(* Logix 5000 project; controller MyControlLogix 1756-L63 rev 15.1; software revision 15.02; part 4 of 4 *)
(* tags used below, declared in another part *)
   AFC56 : AFC;
(* MainProgram, continued *)

ROUTINE Prove_Out   (* ladder *)
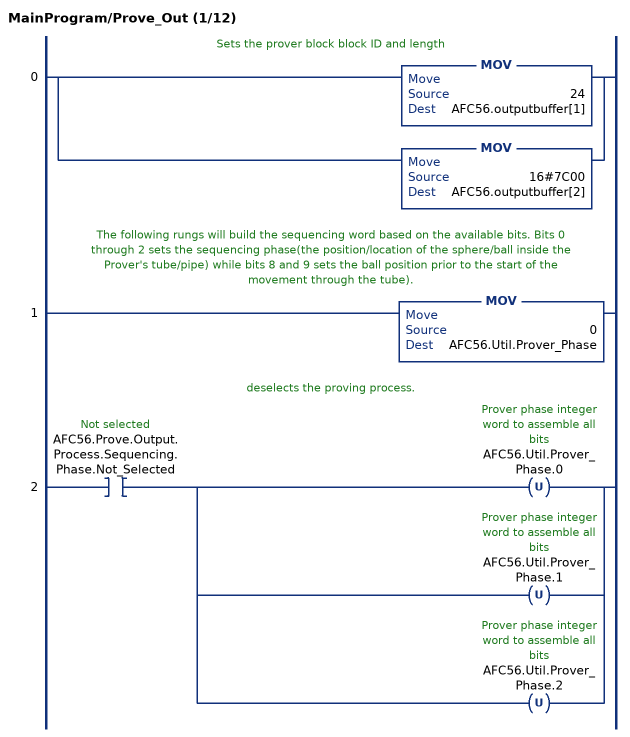
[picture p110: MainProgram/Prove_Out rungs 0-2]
   // Sets the prover block block ID and length
   0: [MOV(24,AFC56.outputbuffer[1]) ,MOV(16#7C00,AFC56.outputbuffer[2]) ];
   // The following rungs will build the sequencing word based on the available bits. Bits 0 through 2 sets the sequencing phase(the position/location of the sphere/ball inside the Prover's tube/pipe) while bits 8 and 9 sets the ball position prior to the start of the movement through the tube).
   1: MOV(0,AFC56.Util.Prover_Phase);
   // deselects the proving process.
   2: XIC(AFC56.Prove.Output.Process.Sequencing.Phase.Not_Selected)[OTU(AFC56.Util.Prover_Phase.0) ,OTU(AFC56.Util.Prover_Phase.1) ,OTU(AFC56.Util.Prover_Phase.2) ];
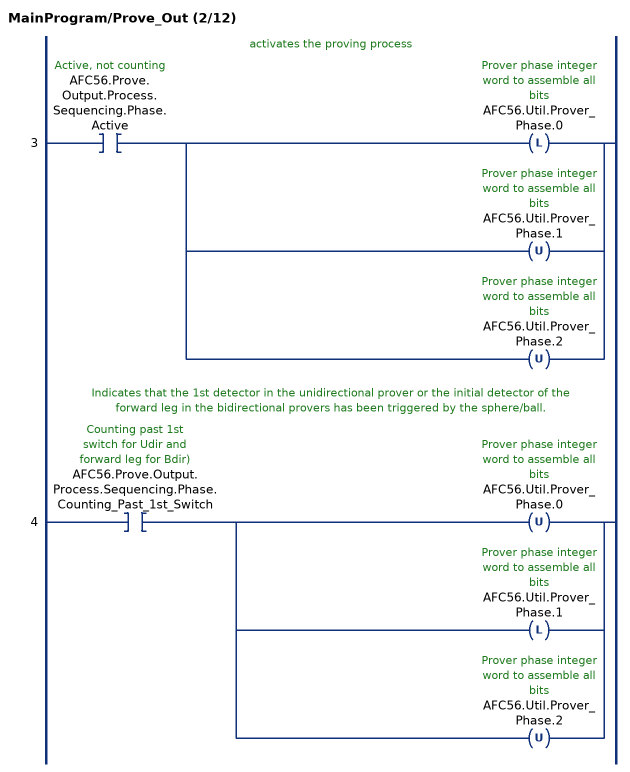
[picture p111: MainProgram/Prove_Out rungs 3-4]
   // activates the proving process
   3: XIC(AFC56.Prove.Output.Process.Sequencing.Phase.Active)[OTL(AFC56.Util.Prover_Phase.0) ,OTU(AFC56.Util.Prover_Phase.1) ,OTU(AFC56.Util.Prover_Phase.2) ];
   // Indicates that the 1st detector in the unidirectional prover or the initial detector of the forward leg in the bidirectional provers has been triggered by the sphere/ball.
   4: XIC(AFC56.Prove.Output.Process.Sequencing.Phase.Counting_Past_1st_Switch)[OTU(AFC56.Util.Prover_Phase.0) ,OTL(AFC56.Util.Prover_Phase.1) ,OTU(AFC56.Util.Prover_Phase.2) ];
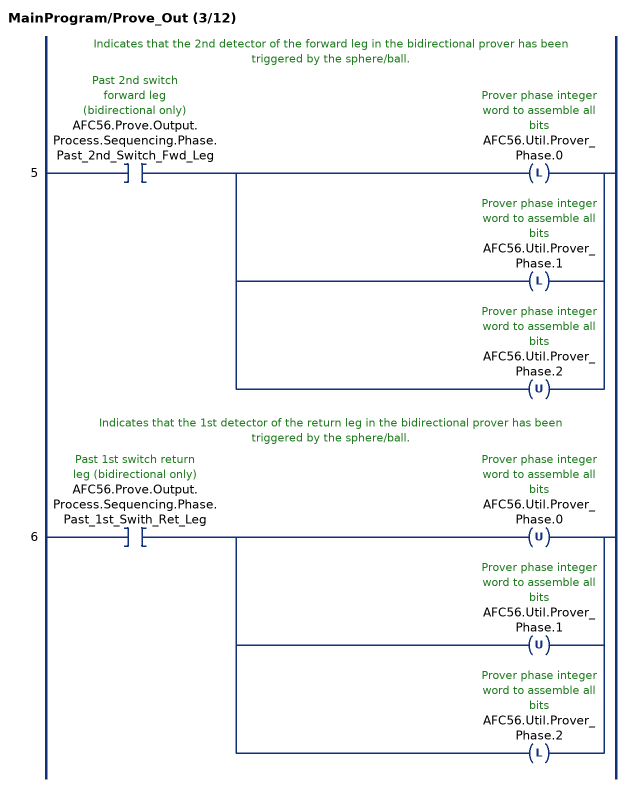
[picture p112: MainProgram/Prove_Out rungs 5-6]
   // Indicates that the 2nd detector of the forward leg in the bidirectional prover has been triggered by the sphere/ball.
   5: XIC(AFC56.Prove.Output.Process.Sequencing.Phase.Past_2nd_Switch_Fwd_Leg)[OTL(AFC56.Util.Prover_Phase.0) ,OTL(AFC56.Util.Prover_Phase.1) ,OTU(AFC56.Util.Prover_Phase.2) ];
   // Indicates that the 1st detector of the return leg in the bidirectional prover has been triggered by the sphere/ball.
   6: XIC(AFC56.Prove.Output.Process.Sequencing.Phase.Past_1st_Swith_Ret_Leg)[OTU(AFC56.Util.Prover_Phase.0) ,OTU(AFC56.Util.Prover_Phase.1) ,OTL(AFC56.Util.Prover_Phase.2) ];
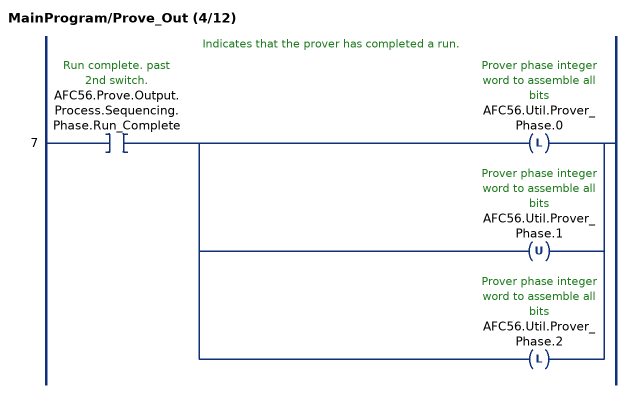
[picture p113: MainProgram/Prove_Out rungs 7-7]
   // Indicates that the prover has completed a run.
   7: XIC(AFC56.Prove.Output.Process.Sequencing.Phase.Run_Complete)[OTL(AFC56.Util.Prover_Phase.0) ,OTU(AFC56.Util.Prover_Phase.1) ,OTL(AFC56.Util.Prover_Phase.2) ];
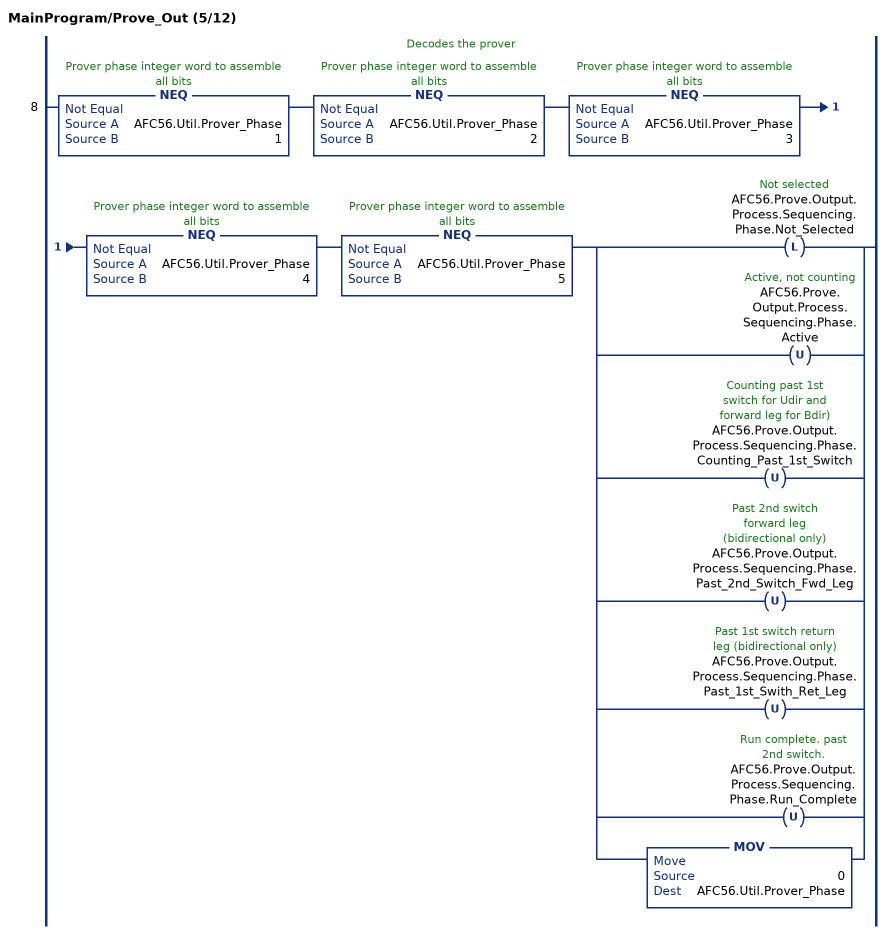
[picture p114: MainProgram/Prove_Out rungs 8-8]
   // Decodes the prover
   8: NEQ(AFC56.Util.Prover_Phase,1)NEQ(AFC56.Util.Prover_Phase,2)NEQ(AFC56.Util.Prover_Phase,3)NEQ(AFC56.Util.Prover_Phase,4)NEQ(AFC56.Util.Prover_Phase,5)[OTL(AFC56.Prove.Output.Process.Sequencing.Phase.Not_Selected) ,OTU(AFC56.Prove.Output.Process.Sequencing.Phase.Active) ,OTU(AFC56.Prove.Output.Process.Sequencing.Phase.Counting_Past_1st_Switch) ,OTU(AFC56.Prove.Output.Process.Sequencing.Phase.Past_2nd_Switch_Fwd_Leg) ,OTU(AFC56.Prove.Output.Process.Sequencing.Phase.Past_1st_Swith_Ret_Leg) ,OTU(AFC56.Prove.Output.Process.Sequencing.Phase.Run_Complete) ,MOV(0,AFC56.Util.Prover_Phase) ];
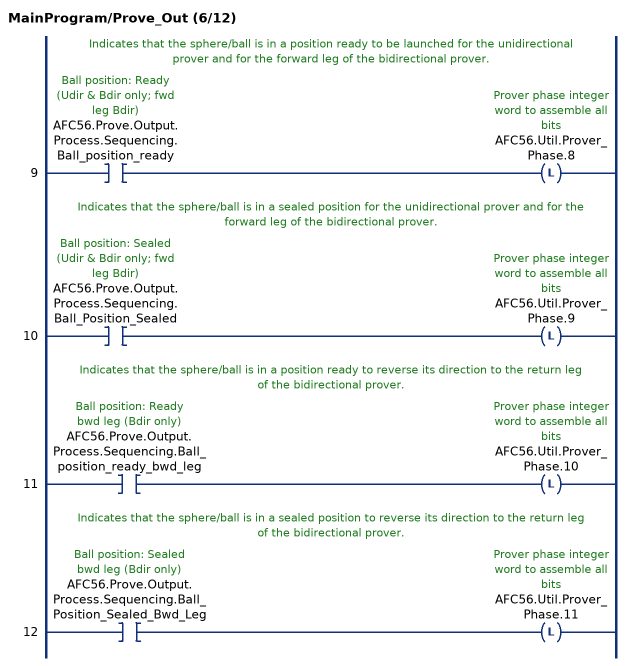
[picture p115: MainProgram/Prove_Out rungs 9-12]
   // Indicates that the sphere/ball is in a position ready to be launched for the unidirectional prover and for the forward leg of the bidirectional prover.
   9: XIC(AFC56.Prove.Output.Process.Sequencing.Ball_position_ready)OTL(AFC56.Util.Prover_Phase.8);
   // Indicates that the sphere/ball is in a sealed position for the unidirectional prover and for the forward leg of the bidirectional prover.
   10: XIC(AFC56.Prove.Output.Process.Sequencing.Ball_Position_Sealed)OTL(AFC56.Util.Prover_Phase.9);
   // Indicates that the sphere/ball is in a position ready to reverse its direction to the return leg of the bidirectional prover.
   11: XIC(AFC56.Prove.Output.Process.Sequencing.Ball_position_ready_bwd_leg)OTL(AFC56.Util.Prover_Phase.10);
   // Indicates that the sphere/ball is in a sealed position to reverse its direction to the return leg of the bidirectional prover.
   12: XIC(AFC56.Prove.Output.Process.Sequencing.Ball_Position_Sealed_Bwd_Leg)OTL(AFC56.Util.Prover_Phase.11);
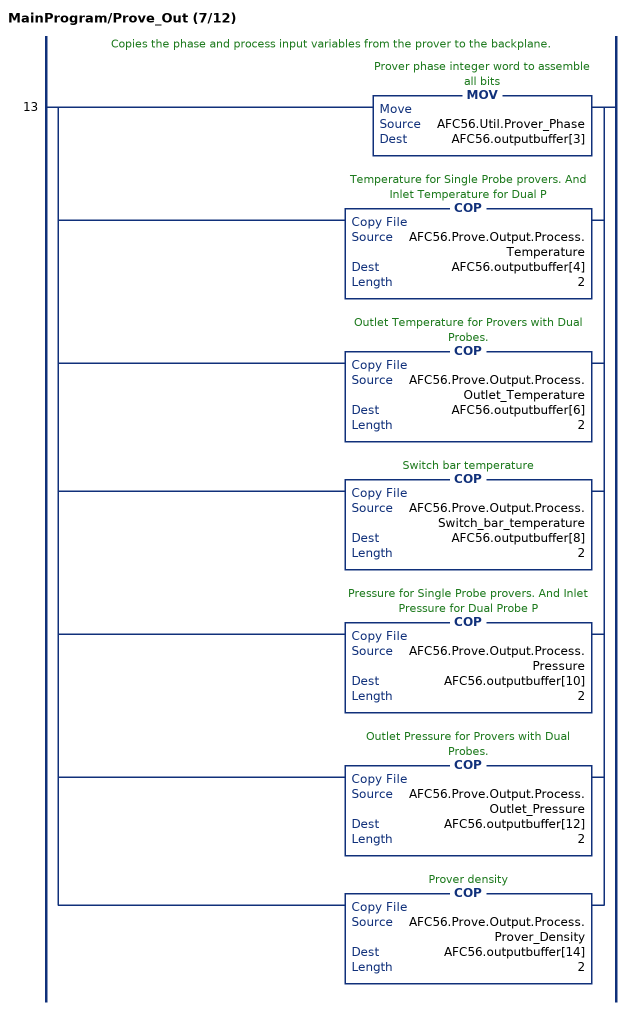
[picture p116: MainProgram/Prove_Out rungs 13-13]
   // Copies the phase and process input variables from the prover to the backplane.
   13: [MOV(AFC56.Util.Prover_Phase,AFC56.outputbuffer[3]) ,COP(AFC56.Prove.Output.Process.Temperature,AFC56.outputbuffer[4],2) ,COP(AFC56.Prove.Output.Process.Outlet_Temperature,AFC56.outputbuffer[6],2) ,COP(AFC56.Prove.Output.Process.Switch_bar_temperature,AFC56.outputbuffer[8],2) ,COP(AFC56.Prove.Output.Process.Pressure,AFC56.outputbuffer[10],2) ,COP(AFC56.Prove.Output.Process.Outlet_Pressure,AFC56.outputbuffer[12],2) ,COP(AFC56.Prove.Output.Process.Prover_Density,AFC56.outputbuffer[14],2) ];
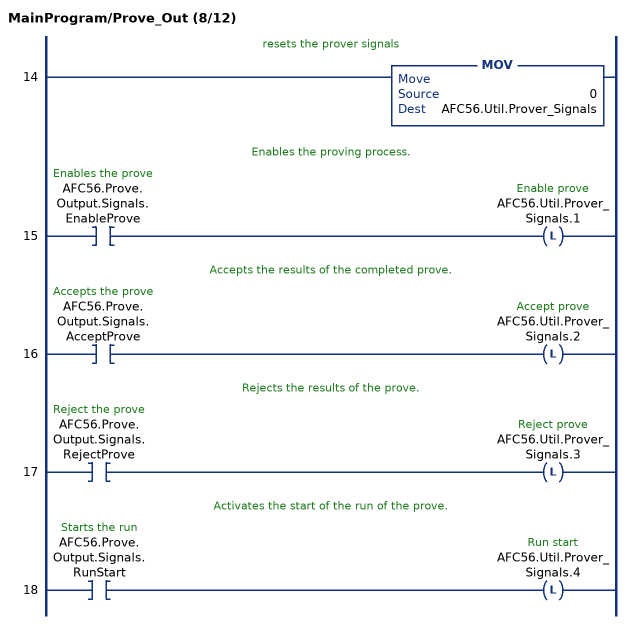
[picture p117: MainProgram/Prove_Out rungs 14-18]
   // resets the prover signals
   14: MOV(0,AFC56.Util.Prover_Signals);
   // Enables the proving process.
   15: XIC(AFC56.Prove.Output.Signals.EnableProve)OTL(AFC56.Util.Prover_Signals.1);
   // Accepts the results of the completed prove.
   16: XIC(AFC56.Prove.Output.Signals.AcceptProve)OTL(AFC56.Util.Prover_Signals.2);
   // Rejects the results of the prove.
   17: XIC(AFC56.Prove.Output.Signals.RejectProve)OTL(AFC56.Util.Prover_Signals.3);
   // Activates the start of the run of the prove.
   18: XIC(AFC56.Prove.Output.Signals.RunStart)OTL(AFC56.Util.Prover_Signals.4);
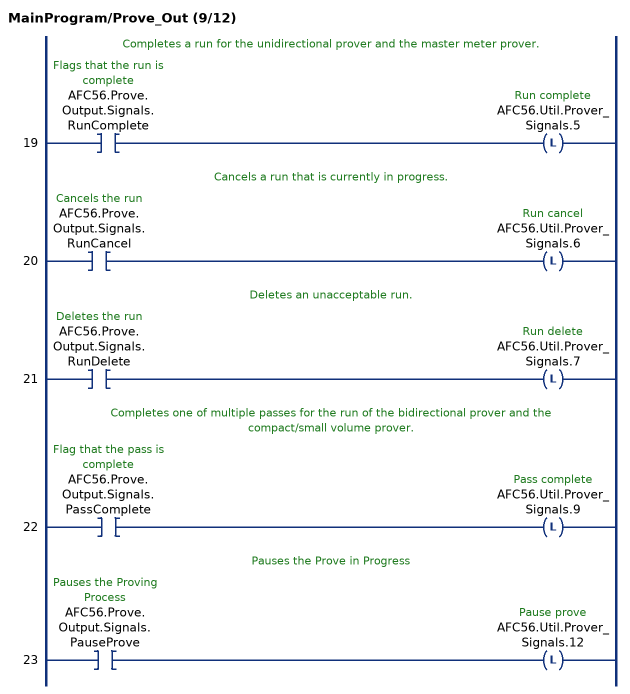
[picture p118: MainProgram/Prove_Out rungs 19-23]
   // Completes a run for the unidirectional prover and the master meter prover.
   19: XIC(AFC56.Prove.Output.Signals.RunComplete)OTL(AFC56.Util.Prover_Signals.5);
   // Cancels a run that is currently in progress.
   20: XIC(AFC56.Prove.Output.Signals.RunCancel)OTL(AFC56.Util.Prover_Signals.6);
   // Deletes an unacceptable run.
   21: XIC(AFC56.Prove.Output.Signals.RunDelete)OTL(AFC56.Util.Prover_Signals.7);
   // Completes one of multiple passes for the run of the bidirectional prover and the compact/small volume prover.
   22: XIC(AFC56.Prove.Output.Signals.PassComplete)OTL(AFC56.Util.Prover_Signals.9);
   // Pauses the Prove in Progress
   23: XIC(AFC56.Prove.Output.Signals.PauseProve)OTL(AFC56.Util.Prover_Signals.12);
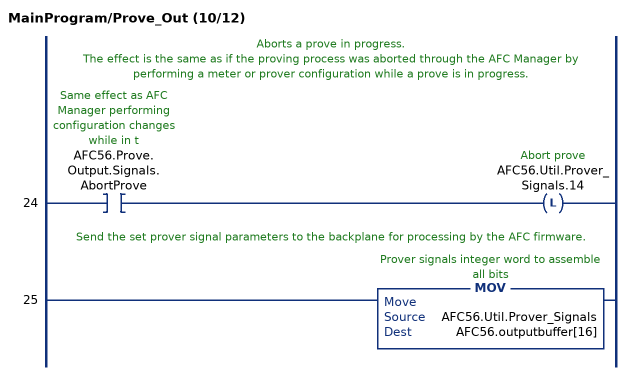
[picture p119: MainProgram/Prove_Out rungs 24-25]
   // Aborts a prove in progress.
   // The effect is the same as if the proving process was aborted through the AFC Manager by performing a meter or prover configuration while a prove is in progress.
   24: XIC(AFC56.Prove.Output.Signals.AbortProve)OTL(AFC56.Util.Prover_Signals.14);
   // Send the set prover signal parameters to the backplane for processing by the AFC firmware.
   25: MOV(AFC56.Util.Prover_Signals,AFC56.outputbuffer[16]);
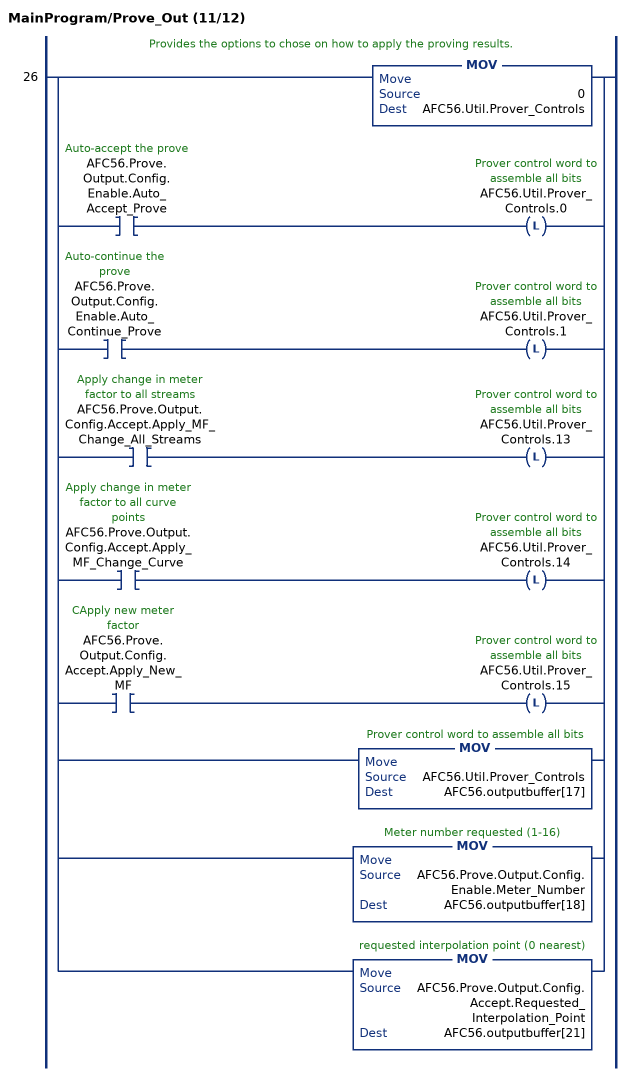
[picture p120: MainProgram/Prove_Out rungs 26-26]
   // Provides the options to chose on how to apply the proving results.
   26: [MOV(0,AFC56.Util.Prover_Controls) ,XIC(AFC56.Prove.Output.Config.Enable.Auto_Accept_Prove) OTL(AFC56.Util.Prover_Controls.0) ,XIC(AFC56.Prove.Output.Config.Enable.Auto_Continue_Prove) OTL(AFC56.Util.Prover_Controls.1) ,XIC(AFC56.Prove.Output.Config.Accept.Apply_MF_Change_All_Streams) OTL(AFC56.Util.Prover_Controls.13) ,XIC(AFC56.Prove.Output.Config.Accept.Apply_MF_Change_Curve) OTL(AFC56.Util.Prover_Controls.14) ,XIC(AFC56.Prove.Output.Config.Accept.Apply_New_MF) OTL(AFC56.Util.Prover_Controls.15) ,MOV(AFC56.Util.Prover_Controls,AFC56.outputbuffer[17]) ,MOV(AFC56.Prove.Output.Config.Enable.Meter_Number,AFC56.outputbuffer[18]) ,MOV(AFC56.Prove.Output.Config.Accept.Requested_Interpolation_Point,AFC56.outputbuffer[21]) ];
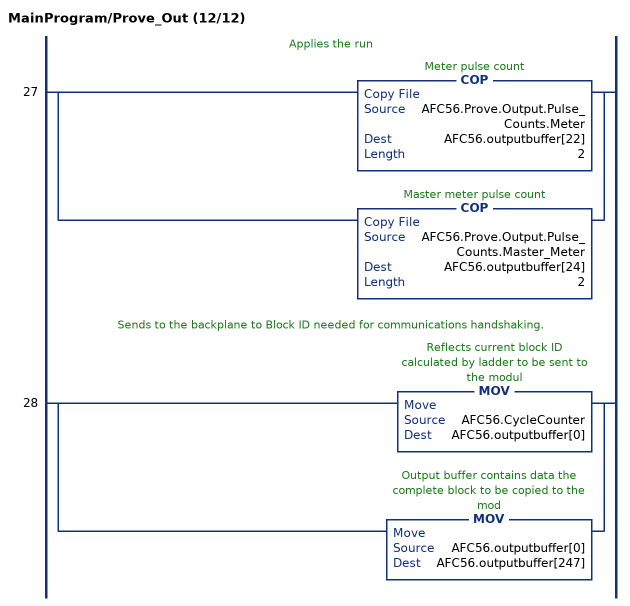
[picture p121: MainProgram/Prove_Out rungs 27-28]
   // Applies the run
   27: [COP(AFC56.Prove.Output.Pulse_Counts.Meter,AFC56.outputbuffer[22],2) ,COP(AFC56.Prove.Output.Pulse_Counts.Master_Meter,AFC56.outputbuffer[24],2) ];
   // Sends to the backplane to Block ID needed for communications handshaking.
   28: [MOV(AFC56.CycleCounter,AFC56.outputbuffer[0]) ,MOV(AFC56.outputbuffer[0],AFC56.outputbuffer[247]) ];
END_ROUTINE

ROUTINE Set_Clock   (* ladder *)
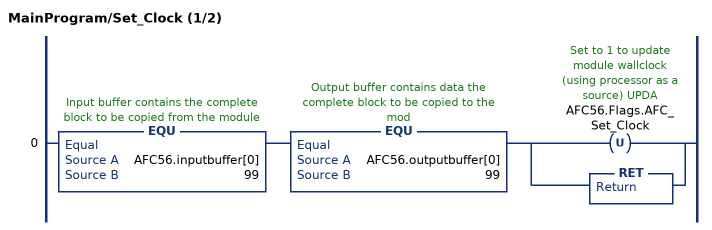
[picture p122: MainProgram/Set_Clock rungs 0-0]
   0: EQU(AFC56.inputbuffer[0],99)EQU(AFC56.outputbuffer[0],99)[OTU(AFC56.Flags.AFC_Set_Clock) ,RET() ];
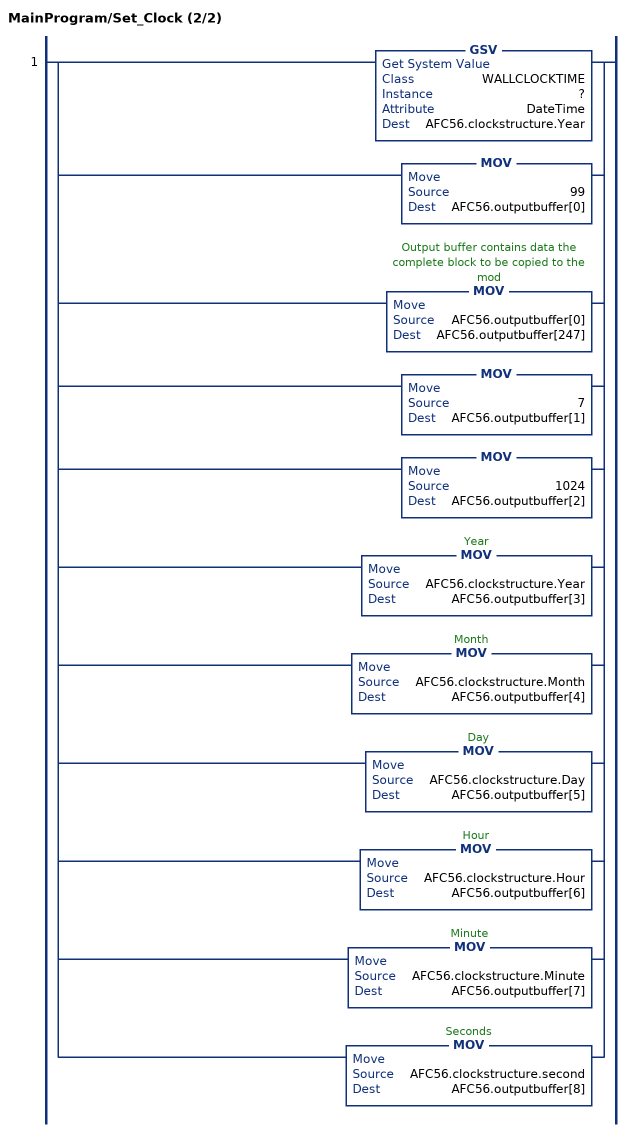
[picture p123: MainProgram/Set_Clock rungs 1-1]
   1: [GSV(WALLCLOCKTIME,?,DateTime,AFC56.clockstructure.Year) ,MOV(99,AFC56.outputbuffer[0]) ,MOV(AFC56.outputbuffer[0],AFC56.outputbuffer[247]) ,MOV(7,AFC56.outputbuffer[1]) ,MOV(1024,AFC56.outputbuffer[2]) ,MOV(AFC56.clockstructure.Year,AFC56.outputbuffer[3]) ,MOV(AFC56.clockstructure.Month,AFC56.outputbuffer[4]) ,MOV(AFC56.clockstructure.Day,AFC56.outputbuffer[5]) ,MOV(AFC56.clockstructure.Hour,AFC56.outputbuffer[6]) ,MOV(AFC56.clockstructure.Minute,AFC56.outputbuffer[7]) ,MOV(AFC56.clockstructure.second,AFC56.outputbuffer[8]) ];
END_ROUTINE
END_PROGRAM
